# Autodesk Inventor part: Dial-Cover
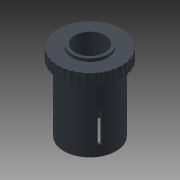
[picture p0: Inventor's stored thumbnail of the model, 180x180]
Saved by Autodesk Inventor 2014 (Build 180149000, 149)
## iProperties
Shininess: 64.0
Length Units: 11272
Angle Units: 11279
Time Units: 11290
Mass Units: 11286
Length Display Precision: 3
Angle Display Precision: 2
Compacted: True
Created: 2001-11
Part Number: Dial-Cover
Document SubType Name: Modeling
Designer: Autodesk, Inc.
Mass: 5.42511 g
Surface Area: 53.7996 cm^2
Volume: 5.42511 cm^3
Density: 1 g/cm^3
Material: Generic
Appearance: Grey (Dark)
Density: 0.0
Volumn: 0.0
Area: 0.0
PropertySet Name: Model Information
Control State: 0
Master: False
Checked Out: False
Author: Autodesk, Inc.
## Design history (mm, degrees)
sketch "Sketch2"
  geometry: L1 (10.006, 24.13)-(6.45, 24.13); L2 (10.006, 0)-(10.006, 24.13); L3 (11.276, 0)-(10.006, 0); L4 (11.276, 28.575)-(11.276, 0); L5 (13.816, 28.575)-(11.276, 28.575); L6 (13.816, 33.274)-(13.816, 28.575); L7 (7.784, 33.274)-(13.816, 33.274); L8 (7.784, 34.544)-(7.784, 33.274); L9 (6.45, 34.544)-(7.784, 34.544); L10 (6.45, 24.13)-(6.45, 34.544); L11 (0, 0)-(0, 34.056); 1 further point
  constraints: 22 end point, 5 horizontal, 5 vertical, 1 coincident, 1 horizontal alignment
  dimensions: "d15" = 12.90092 diameter of L10 L11; "d16" = 15.56792 diameter of L8 L11; "d17" = 10.414 distance of L1.end L9.start; "d18" = 4.699 distance of L6.start L5.start; "d19" = 6.0325 distance of L7.start L6.start; "d20" = 2.54 distance of L5.start L4.start; "d21" = 28.575 distance of L4.start L3.start; "d22" = 20.01292 diameter of L2 L11; "d23" = 1.27 distance of L8.start L7.start
revolve "RevolutionFull1" sketch "Sketch2" stored, may be unused: angle "d0" = 360 deg
sketch "Sketch3"
  geometry: L1 (-0.635, 17.287)-(0.635, 17.287); L2 (0.635, 17.287)-(0.635, 4.587); L3 (-0.635, 4.587)-(0.635, 4.587); L4 (-0.635, 17.287)-(-0.635, 4.587); L5 (0, -1.15)-(0, 39.011) reference; 1 further point
  constraints: 8 end point, 2 horizontal, 2 vertical, 1 midpoint, 1 point on line
  dimensions: "d24" = 12.7 distance of L1.end L2.end; "d25" = 1.27 distance of L1.start L1.end
extrude "ExtrusionMidplane1" cut sketch "Sketch3" stored distance "d1" = 127; taper "d2" = 0 deg
pattern_circular "PolarArray1" dims angle "d7" = 360 deg
sketch "Sketch6"
  geometry: C1 r 1.27 at (-14.854, 0)
  constraints: 1 centre point
  dimensions: "d9" = 2.54 diameter of C1
extrude "ExtrusionToPlane1" cut sketch "Sketch6" stored distance "d10" = 3.302; taper "d11" = 0 deg
node "Sketch7"
body "Solid1"
pattern_circular "Circular Pattern3" dims angle "d28" = 360 deg
other parameters: "d3" = 0, "d4" = 0, "d8" = 2.54 (derived)
